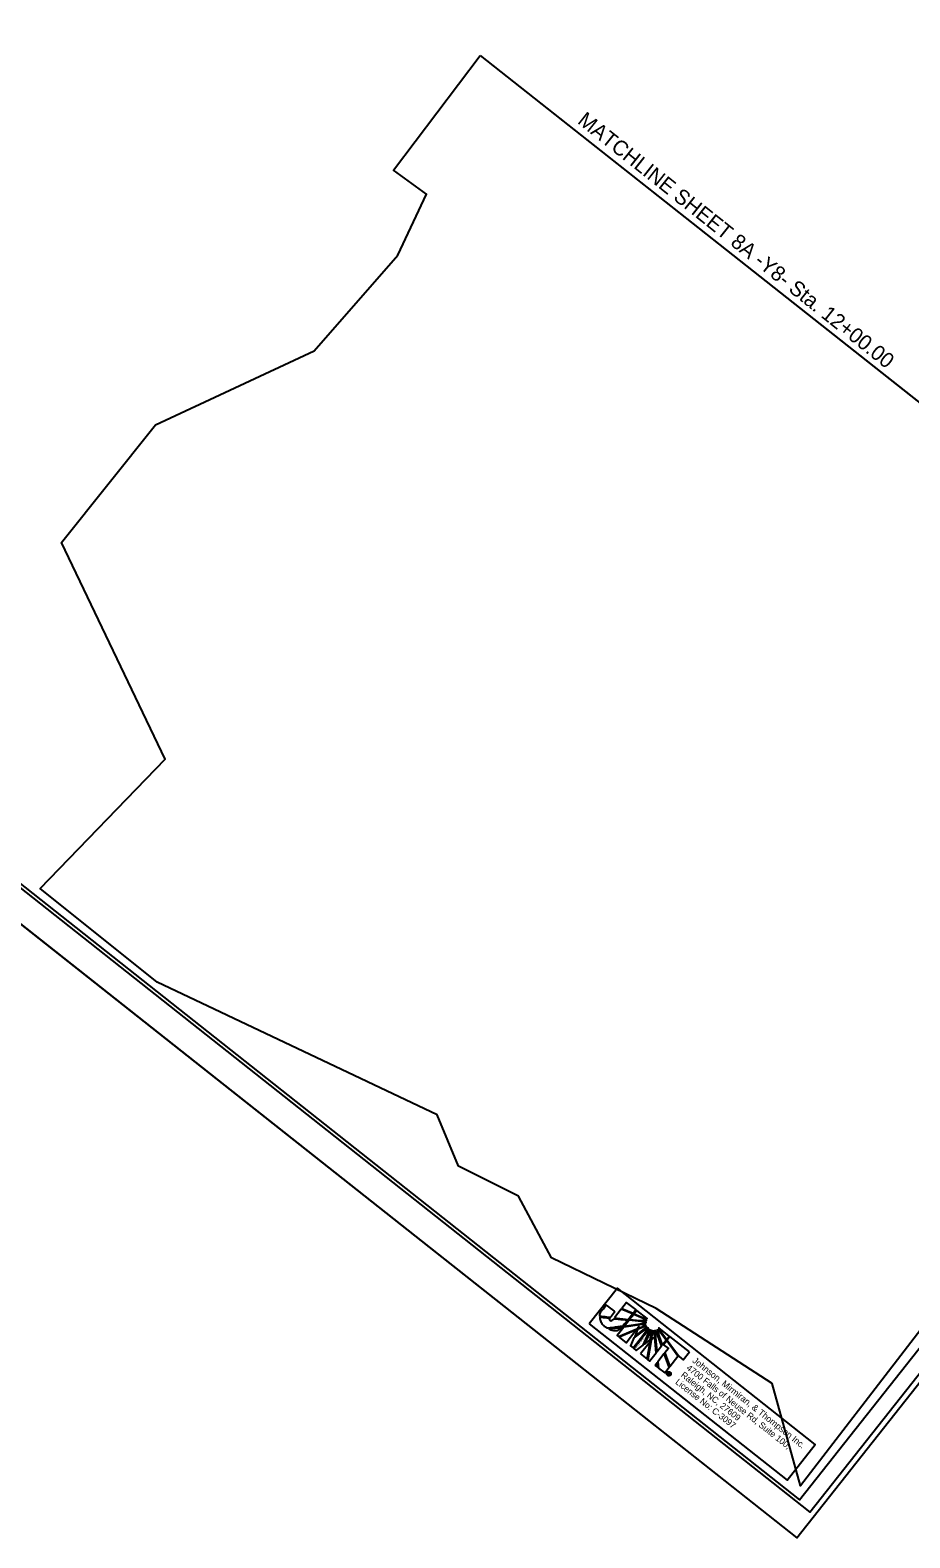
# Model space of a CAD drawing. Extents: x 556999 to 559002, y 505273 to 507273.
# Drawn here: x 557712 to 558410, y 505366 to 506562 of the extents above; entities that cross this region are included whole.
import ezdxf

# ---------------------------------------------------------------- set-up
doc = ezdxf.new("R2010")
doc.units = 0
for name, color, linetype in [('Matchline', 7, 'Continuous'), ('Matchline Text', 7, 'Continuous'), ('Prop Dimension Text', 7, 'Continuous'), ('Prop Horizontal Alignment Direction Label', 7, 'Continuous'), ('Prop SS Cut Line', 7, 'Continuous'), ('Prop SS Fill Line', 7, 'Continuous'), ('Scratch_Level_9', 7, 'Continuous'), ('Sheet Clip Boundary CELL', 7, 'Continuous')]:
    doc.layers.add(name, color=color, linetype=linetype)

msp = doc.modelspace()

# ---------------------------------------------------------------- linework, layer by layer
at = {"layer": 'Matchline'}
msp.add_line((558069.1, 506542.3), (558502.2, 506199.9), dxfattribs=at)
at = {"layer": 'Prop Dimension Text'}
for p, q in [((558180.9, 505547.3), (558175.5, 505540.5)), ((558189.8, 505543.6), (558180.9, 505547.3)), ((558185.2, 505552.8), (558181.3, 505547.9)), ((558181.3, 505547.9), (558190.3, 505544.1)), ((558192.5, 505547), (558185.2, 505552.8)), ((558186.5, 505539.3), (558189.8, 505543.6)), ((558190.8, 505543.2), (558187.6, 505539.2)), ((558190.3, 505544.1), (558192.5, 505547)), ((558198.3, 505540), (558190.8, 505543.2)), ((558193.3, 505546.4), (558191.2, 505543.8)), ((558191.2, 505543.8), (558198.7, 505540.6)), ((558201.6, 505539.9), (558193.3, 505546.4)), ((558175.5, 505540.5), (558186.5, 505539.3)), ((558182.9, 505533.2), (558177.6, 505526.6)), ((558178.8, 505525.6), (558193.4, 505531.7)), ((558192.6, 505530.7), (558179.4, 505525.1)), ((558197.6, 505535.3), (558182.9, 505533.2)), ((558187.1, 505538.6), (558183.5, 505534)), ((558183.5, 505534), (558197.6, 505535.9)), ((558184.9, 505520.8), (558192.6, 505530.7)), ((558196.7, 505537.6), (558187.1, 505538.6)), ((558187.6, 505539.2), (558195.9, 505538.4)), ((558199.4, 505530.9), (558191, 505524.6)), ((558191.6, 505525.8), (558199.3, 505531.7)), ((558193.9, 505531.2), (558191.6, 505525.8)), ((558193.4, 505531.7), (558194.9, 505533.7)), ((558198.4, 505533.1), (558193.9, 505531.2)), ((558194.9, 505533.7), (558194.3, 505532)), ((558194.3, 505532), (558198, 505533.6)), ((558195.9, 505538.4), (558200.9, 505538.4)), ((558200.6, 505536.8), (558196.7, 505537.6)), ((558197.6, 505535.9), (558200.6, 505536.8)), ((558200.8, 505535.3), (558197.6, 505535.3)), ((558198, 505533.6), (558200.8, 505535.3)), ((558198, 505526.4), (558202.3, 505532.5)), ((558200.9, 505538.4), (558198.3, 505540)), ((558201.3, 505533.8), (558198.4, 505533.1)), ((558203.5, 505531.5), (558198.5, 505526)), ((558198.7, 505540.6), (558201.6, 505539.9)), ((558199.3, 505531.7), (558201.3, 505533.8)), ((558202.3, 505532.5), (558199.4, 505530.9)), ((558202.6, 505528.4), (558203.5, 505531.5)), ((558204.9, 505530.9), (558203.3, 505528.4)), ((558204.8, 505527.9), (558204.9, 505530.9)), ((558206.5, 505530.8), (558205.5, 505527.7)), ((558207.2, 505527.7), (558206.5, 505530.8)), ((558208, 505531), (558207.8, 505527.8)), ((558209.7, 505527.3), (558208, 505531)), ((558209.6, 505531.6), (558210.7, 505526.6)), ((558211.6, 505529.5), (558209.6, 505531.6)), ((558219, 505526), (558210.9, 505532.5)), ((558210.9, 505532.5), (558212.2, 505529.9)), ((558177.6, 505526.6), (558178.8, 505525.6)), ((558179.4, 505525.1), (558184.9, 505520.8)), ((558191, 505524.6), (558188.2, 505518.2)), ((558188.2, 505518.2), (558190.3, 505516.6)), ((558190.3, 505516.6), (558198, 505526.4)), ((558198.5, 505526), (558190.8, 505516.2)), ((558192.8, 505514.6), (558198.3, 505518.7)), ((558203.8, 505521.5), (558196.2, 505511.9)), ((558198.3, 505518.7), (558202.6, 505528.4)), ((558203.3, 505528.4), (558199.3, 505519.5)), ((558199.3, 505519.5), (558204, 505523)), ((558201.5, 505507.8), (558203.8, 505521.5)), ((558204.6, 505522.5), (558202.1, 505507.3)), ((558204, 505523), (558204.8, 505527.9)), ((558206.3, 505524.7), (558204.6, 505522.5)), ((558205.5, 505527.7), (558204.8, 505523.5)), ((558204.8, 505523.5), (558206.3, 505524.7)), ((558208.6, 505512.8), (558207.2, 505527.7)), ((558207.8, 505527.8), (558209.2, 505513.6)), ((558209.2, 505513.6), (558212.9, 505518.3)), ((558212.9, 505518.3), (558209.7, 505527.3)), ((558210.7, 505526.6), (558213.4, 505519)), ((558216.5, 505522.8), (558211.6, 505529.5)), ((558212.2, 505529.9), (558217, 505523.4)), ((558213.4, 505519), (558216.5, 505522.8)), ((558217, 505522.2), (558214.6, 505519.2)), ((558214.6, 505519.2), (558218.4, 505516.3)), ((558217, 505523.4), (558219, 505526)), ((558217, 505522.2), (558217, 505522.2)), ((558225.8, 505510), (558217, 505522.2)), ((558217.4, 505522.8), (558217.3, 505522.7)), ((558217.3, 505522.7), (558226.8, 505509.7)), ((558219.6, 505525.6), (558217.4, 505522.8)), ((558235.1, 505513.4), (558219.6, 505525.6)), ((558190.8, 505516.2), (558192.8, 505514.6)), ((558196.2, 505511.9), (558201.5, 505507.8)), ((558202.1, 505507.3), (558203.4, 505506.2)), ((558203.4, 505506.2), (558208.6, 505512.8)), ((558215.1, 505512.1), (558209.9, 505505.6)), ((558219, 505501.3), (558215.1, 505512.1)), ((558218.4, 505516.3), (558215.6, 505512.7)), ((558215.6, 505512.7), (558219.4, 505501.9)), ((558219.4, 505501.9), (558225.8, 505510)), ((558226.8, 505509.7), (558230.1, 505507.1)), ((558230.1, 505507.1), (558235.1, 505513.4)), ((558209.4, 505504.8), (558207.8, 505502.8)), ((558207.8, 505502.8), (558209.7, 505501.3)), ((558209.7, 505501.3), (558209.4, 505504.8)), ((558209.9, 505505.6), (558210.4, 505500.7)), ((558210.4, 505500.7), (558215.4, 505496.8)), ((558215.4, 505496.8), (558219, 505501.3)), ((558218, 505495.1), (558217.8, 505494.9)), ((558217.8, 505494.9), (558218, 505495.1)), ((558217.8, 505494.9), (558217.8, 505494.9)), ((558217.9, 505495.9), (558218.7, 505497.1)), ((558218.1, 505495.7), (558217.9, 505495.9)), ((558218, 505495.1), (558218, 505495.1)), ((558218.5, 505496.2), (558218.1, 505495.7)), ((558218.7, 505496), (558218.5, 505496.2)), ((558218.8, 505496.6), (558218.6, 505496.4)), ((558218.6, 505496.4), (558218.8, 505496.2)), ((558218.7, 505497.1), (558219.2, 505496.7)), ((558218.8, 505496.2), (558218.7, 505496)), ((558218.7, 505496), (558218.8, 505496.2)), ((558218.7, 505496), (558218.7, 505496)), ((558219, 505496.5), (558218.8, 505496.6)), ((558218.8, 505496.2), (558218.8, 505496.2)), ((558219.2, 505496.7), (558219, 505496.5)), ((558219, 505496.5), (558219.2, 505496.7)), ((558219.1, 505496.5), (558219, 505496.5)), ((558219.2, 505496.7), (558219.3, 505496.6)), ((558219.7, 505497.4), (558219.5, 505497.1)), ((558219.5, 505497.1), (558219.7, 505497.4))]:
    msp.add_line(p, q, dxfattribs=at)
msp.add_lwpolyline([(558155.6, 505535.8), (558312.5, 505411.7), (558334.9, 505440), (558178, 505564.1)], close=True, dxfattribs=at)
for points in [[(558175.5, 505540.5), (558186.5, 505539.3), (558189.8, 505543.6), (558180.9, 505547.3), (558175.5, 505540.5)], [(558181.3, 505547.9), (558190.3, 505544.1), (558192.5, 505547), (558185.2, 505552.8), (558181.3, 505547.9)], [(558190.8, 505543.2), (558187.6, 505539.2), (558195.9, 505538.4), (558200.9, 505538.4), (558198.3, 505540), (558190.8, 505543.2)], [(558198.7, 505540.6), (558201.6, 505539.9), (558193.3, 505546.4), (558191.2, 505543.8), (558198.7, 505540.6)], [(558200.8, 505535.3), (558197.6, 505535.3), (558182.9, 505533.2), (558177.6, 505526.6), (558178.8, 505525.6), (558193.4, 505531.7), (558194.9, 505533.7), (558194.3, 505532), (558198, 505533.6), (558200.8, 505535.3)], [(558179.4, 505525.1), (558184.9, 505520.8), (558192.6, 505530.7), (558179.4, 505525.1)], [(558187.1, 505538.6), (558183.5, 505534), (558197.6, 505535.9), (558200.6, 505536.8), (558196.7, 505537.6), (558187.1, 505538.6)], [(558199.4, 505530.9), (558191, 505524.6), (558188.2, 505518.2), (558190.3, 505516.6), (558198, 505526.4), (558202.3, 505532.5), (558199.4, 505530.9)], [(558203.5, 505531.5), (558198.5, 505526), (558190.8, 505516.2), (558192.8, 505514.6), (558198.3, 505518.7), (558202.6, 505528.4), (558203.5, 505531.5)], [(558201.3, 505533.8), (558198.4, 505533.1), (558193.9, 505531.2), (558191.6, 505525.8), (558199.3, 505531.7), (558201.3, 505533.8)], [(558204.9, 505530.9), (558203.3, 505528.4), (558199.3, 505519.5), (558204, 505523), (558204.8, 505527.9), (558204.9, 505530.9)], [(558206.5, 505530.8), (558205.5, 505527.7), (558204.8, 505523.5), (558206.3, 505524.7), (558204.6, 505522.5), (558202.1, 505507.3), (558203.4, 505506.2), (558208.6, 505512.8), (558207.2, 505527.7), (558206.5, 505530.8)], [(558208, 505531), (558207.8, 505527.8), (558209.2, 505513.6), (558212.9, 505518.3), (558209.7, 505527.3), (558208, 505531)], [(558209.6, 505531.6), (558210.7, 505526.6), (558213.4, 505519), (558216.5, 505522.8), (558211.6, 505529.5), (558209.6, 505531.6)], [(558212.2, 505529.9), (558217, 505523.4), (558219, 505526), (558210.9, 505532.5), (558212.2, 505529.9)], [(558196.2, 505511.9), (558201.5, 505507.8), (558203.8, 505521.5), (558196.2, 505511.9)], [(558217, 505522.2), (558217, 505522.2), (558214.6, 505519.2), (558218.4, 505516.3), (558215.6, 505512.7), (558219.4, 505501.9), (558225.8, 505510), (558217, 505522.2)], [(558235.1, 505513.4), (558219.6, 505525.6), (558217.4, 505522.8), (558217.3, 505522.7), (558226.8, 505509.7), (558230.1, 505507.1), (558235.1, 505513.4)], [(558215.1, 505512.1), (558209.9, 505505.6), (558210.4, 505500.7), (558215.4, 505496.8), (558219, 505501.3), (558215.1, 505512.1), (558215.1, 505512.1)], [(558207.8, 505502.8), (558207.8, 505502.8), (558209.7, 505501.3), (558209.4, 505504.8), (558207.8, 505502.8)], [(558219, 505495.5), (558219, 505495.4), (558218.9, 505495.3), (558218.9, 505495.3), (558218.8, 505495.2), (558218.6, 505495.3)]]:
    msp.add_lwpolyline(points, dxfattribs=at)
for points, degree in [([(558175.8, 505545.3), (558175.8, 505545.3), (558169, 505550.7), (558169, 505550.7), (558169, 505550.7), (558165.7, 505546.4), (558165.7, 505546.4), (558165.7, 505546.4), (558165.3, 505546), (558165.3, 505546), (558164.3, 505544.6), (558163.9, 505543.2), (558164, 505541.7), (558164, 505541.7), (558172.2, 505540.7), (558172.3, 505540.8), (558172.3, 505540.8), (558175.8, 505545.3), (558175.8, 505545.3)], 3), ([(558172.1, 505538.3), (558171.6, 505538.7), (558171.4, 505539.2), (558171.9, 505540.2), (558171.9, 505540.2), (558164.1, 505541.1), (558164.1, 505541.1), (558164.4, 505538.1), (558166.1, 505535), (558168.3, 505533.3), (558168.9, 505532.8), (558169.4, 505532.5), (558170.1, 505532.2), (558170.1, 505532.2), (558182.1, 505533.8), (558182.1, 505533.8), (558182.1, 505533.8), (558186, 505538.7), (558186, 505538.7), (558186, 505538.7), (558175, 505539.9), (558175, 505539.9), (558173.5, 505538), (558172.7, 505537.9), (558172.1, 505538.3)], 3), ([(558172.1, 505538.3), (558171.6, 505538.7), (558171.4, 505539.2), (558171.9, 505540.2), (558171.9, 505540.2), (558164.1, 505541.1), (558164.1, 505541.1), (558164.4, 505538.1), (558166.1, 505535), (558168.3, 505533.3), (558168.9, 505532.8), (558169.4, 505532.5), (558170.1, 505532.2), (558170.1, 505532.2), (558182.1, 505533.8), (558182.1, 505533.8), (558182.1, 505533.8), (558186, 505538.7), (558186, 505538.7), (558186, 505538.7), (558175, 505539.9), (558175, 505539.9), (558173.5, 505538), (558172.7, 505537.9), (558172.1, 505538.3)], 3), ([(558181.5, 505533), (558181.5, 505533), (558171.1, 505531.6), (558171.1, 505531.6), (558174.5, 505530.1), (558178.7, 505529.8), (558181.5, 505533)], 3), ([(558217.8, 505494.9), (558217.4, 505495.2), (558217.2, 505495.5), (558217.2, 505496), (558217.1, 505496.4), (558217.2, 505496.8), (558217.5, 505497.1), (558217.8, 505497.5), (558218.1, 505497.7), (558218.6, 505497.7), (558219, 505497.7), (558219.4, 505497.6), (558219.7, 505497.4)], 3), ([(558219.5, 505497.1), (558219.3, 505497.3), (558219, 505497.4), (558218.6, 505497.4), (558218.3, 505497.4), (558218, 505497.2), (558217.8, 505496.9), (558217.5, 505496.7), (558217.4, 505496.3), (558217.5, 505496), (558217.5, 505495.6), (558217.7, 505495.4), (558218, 505495.1)], 3), ([(558220, 505495.1), (558219.7, 505494.8), (558219.4, 505494.6), (558219, 505494.5), (558218.5, 505494.5), (558218.1, 505494.6), (558217.8, 505494.9)], 3), ([(558218, 505495.1), (558218.3, 505494.9), (558218.6, 505494.8), (558218.9, 505494.9), (558219.3, 505494.9), (558219.5, 505495.1), (558219.8, 505495.3), (558220, 505495.6), (558220.1, 505495.9), (558220, 505496.3), (558220, 505496.6), (558219.8, 505496.9), (558219.5, 505497.1)], 3), ([(558218.6, 505495.3), (558218.6, 505495.4), (558218.7, 505495.5), (558218.7, 505495.6), (558218.8, 505495.7), (558218.8, 505495.8), (558218.8, 505495.8)], 3), ([(558218.8, 505495.8), (558218.8, 505495.9), (558218.8, 505495.9), (558218.7, 505496)], 2), ([(558218.8, 505496.2), (558219, 505496.1), (558219.1, 505496.1), (558219.2, 505496.2), (558219.3, 505496.2), (558219.2, 505496.3), (558219.1, 505496.5)], 3), ([(558219.1, 505495.8), (558219.1, 505495.7), (558219.1, 505495.6), (558219, 505495.5)], 2), ([(558219.3, 505496.6), (558219.6, 505496.4), (558219.6, 505496.2), (558219.4, 505496), (558219.4, 505495.9), (558219.2, 505495.8), (558219.1, 505495.8)], 3), ([(558219.7, 505497.4), (558220.1, 505497.1), (558220.3, 505496.7), (558220.3, 505496.3), (558220.4, 505495.9), (558220.3, 505495.5), (558220, 505495.1)], 3)]:
    msp.add_open_spline(points, degree=degree, dxfattribs=at)
at = {"layer": 'Prop Horizontal Alignment Direction Label'}
msp.add_lwpolyline([(559002.4, 506228.8), (557681.5, 507273.3), (556999.2, 506410.4), (558320.2, 505365.9)], close=True, dxfattribs=at)
at = {"layer": 'Prop SS Cut Line'}
msp.add_lwpolyline([(558973.6, 506219.7), (557797, 507150.1), (557145.7, 506326.4), (558322.3, 505396.1)], close=True, dxfattribs=at)
at = {"layer": 'Prop SS Fill Line'}
msp.add_lwpolyline([(558985, 506214), (557677.7, 507247.6), (557023.3, 506419.9), (558330.6, 505386.3)], close=True, dxfattribs=at)
at = {"layer": 'Scratch_Level_9'}
msp.add_line((556999.2, 506410.4), (558320.2, 505365.9), dxfattribs=at)
at = {"layer": 'Sheet Clip Boundary CELL'}
msp.add_lwpolyline([(558069.1, 506542.3), (558502.2, 506199.9), (558564.3, 506127), (558761.1, 505975.8), (558323.2, 505407.1), (558300.8, 505488.4), (558208.7, 505547.9), (558125.5, 505588.2), (558099.5, 505637.1), (558051.9, 505660.9), (558034.9, 505701.5), (557812.5, 505806.8), (557719.9, 505881.2), (557819.1, 505983.9), (557736.7, 506155.7), (557811.4, 506249.2), (557937.1, 506307.8), (558003.5, 506383.7), (558026.5, 506432.2), (558000.1, 506451.2)], close=True, dxfattribs=at)

# ---------------------------------------------------------------- texts
at = {"layer": 'Matchline Text'}
msp.add_text('MATCHLINE SHEET 8A -Y8- Sta. 12+00.00', height=12, rotation=321.4798, dxfattribs=at).set_placement((558145.5, 506489))
at = {"layer": 'Prop Dimension Text'}
for s, height, rotation, p in [('www.jmt.com', 1.241, 231.6667, (558198.2, 505524.6)), ('Johnson, Mirmiran, & Thompson Inc.', 5.111, 321.6667, (558236.9, 505505.7)), ('Raleigh, NC, 27609', 4.965, 321.6667, (558227.8, 505494.3)), ('4700 Falls of Neuse Rd, Suite 100, ', 4.965, 321.6667, (558232.2, 505499.9)), ('License No: C-3097', 4.965, 321.6667, (558223.4, 505488.7))]:
    msp.add_text(s, height=height, rotation=rotation, dxfattribs=at).set_placement(p)

doc.saveas('drawing.dxf')
